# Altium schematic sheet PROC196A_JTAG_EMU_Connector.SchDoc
size 431 x 279 mm; Date: Not shown in title block; ApprovedBy: Not shown in title block; CheckedBy: Not shown in title block; Author: Not shown in title block; CompanyName: Not shown in title block; Engineer: Not shown in title block; Organization: Not shown in title block; Address1: Not shown in title block; Address2: Not shown in title block; Address3: Not shown in title block; Address4: Not shown in title block; DocumentNumber: 20; Revision: Use project parameter SCH_Rev; SheetNumber: 20; SheetTotal: 25; PageSetup: Record=PageOptions¦CenterHorizontal=True¦CenterVertical=True¦PrintScale=1.00¦XCorrection=1.00¦YCorrection=1.00¦PrintKind=0¦BorderSize=5000000¦LeftOffset=0¦BottomOffset=0¦Orientation=2¦PaperLength=1000¦PaperWidth=1000¦Scale=100¦PaperSource=15¦PrintQuality=600¦MediaType=1¦DitherType=10¦PaperKind=Letter¦PrintScaleMode=1
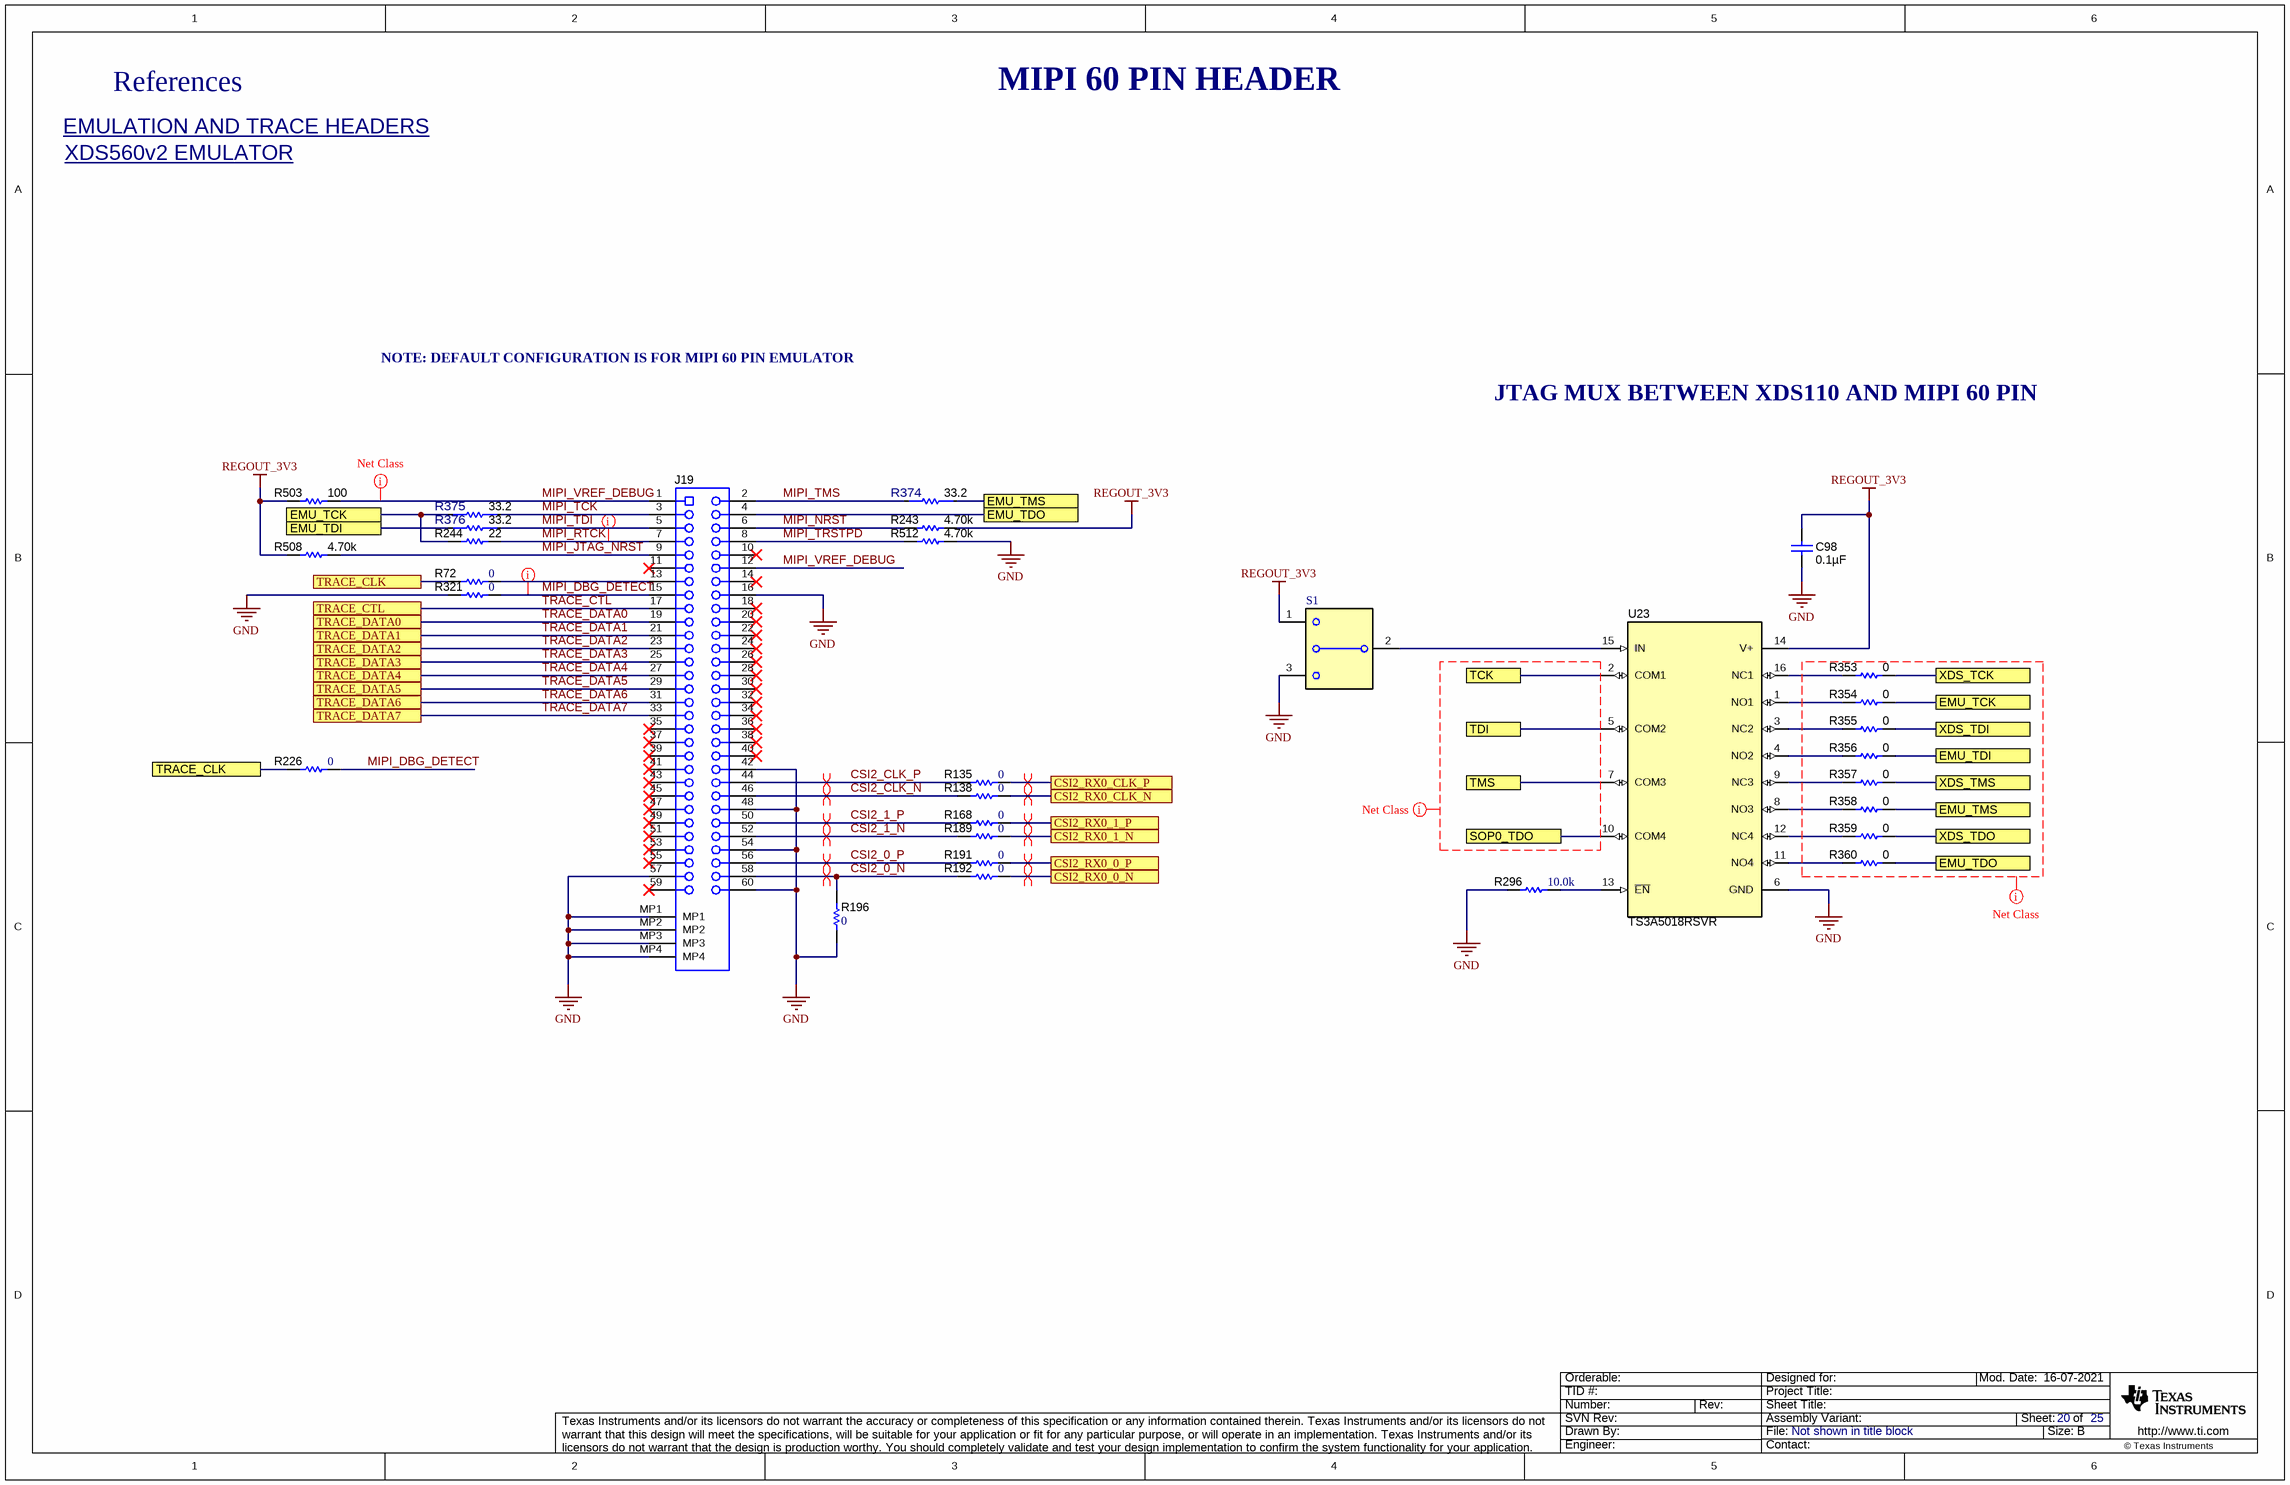
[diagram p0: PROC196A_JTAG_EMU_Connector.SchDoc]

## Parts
C98  ValueDisplayed: 0.1µF  [0402L]  (hidden comment: C0402C104K8RACTU)
J19  Receptacle_30x2_4MP_LeftRight  [Samtec_QSH-030-01-X-D-A]  (value not drawn)
R72  ValueDisplayed: 0  [0201L]  (hidden comment: CRCW02010000Z0ED)
R135  ValueDisplayed: 0  [0201L]  (hidden comment: CRCW02010000Z0ED)
R138  ValueDisplayed: 0  [0201L]  (hidden comment: CRCW02010000Z0ED)
R168  ValueDisplayed: 0  [0201L]  (hidden comment: CRCW02010000Z0ED)
R189  ValueDisplayed: 0  [0201L]  (hidden comment: CRCW02010000Z0ED)
R191  ValueDisplayed: 0  [0201L]  (hidden comment: CRCW02010000Z0ED)
R192  ValueDisplayed: 0  [0201L]  (hidden comment: CRCW02010000Z0ED)
R196  ValueDisplayed: 0  [0201L]  (hidden comment: CRCW02010000Z0ED)
R226  ValueDisplayed: 0  [0201L]  (hidden comment: CRCW02010000Z0ED)
R243  ValueDisplayed: 4.70k  [0201_033L]  (hidden comment: CRCW02014K70FKED)
R244  ValueDisplayed: 22  [0201L]  (hidden comment: ERJ-1GNJ220C)
R296  ValueDisplayed: 10.0k  [0402L]  (hidden comment: CRCW040210K0FKED)
R321  ValueDisplayed: 0  [0201L]  (hidden comment: CRCW02010000Z0ED)
R353  ValueDisplayed: 0  [0402L]  (hidden comment: ERJ-2GE0R00X)
R354  ValueDisplayed: 0  [0402L]  (hidden comment: ERJ-2GE0R00X)
R355  ValueDisplayed: 0  [0402L]  (hidden comment: ERJ-2GE0R00X)
R356  ValueDisplayed: 0  [0402L]  (hidden comment: ERJ-2GE0R00X)
R357  ValueDisplayed: 0  [0402L]  (hidden comment: ERJ-2GE0R00X)
R358  ValueDisplayed: 0  [0402L]  (hidden comment: ERJ-2GE0R00X)
R359  ValueDisplayed: 0  [0402L]  (hidden comment: ERJ-2GE0R00X)
R360  ValueDisplayed: 0  [0402L]  (hidden comment: ERJ-2GE0R00X)
R374  Res_ohm: 33.2  [FP-ERJ-1GNF33R2C_0201-MFG]  (hidden comment: ERJ-1GNF33R2C)
R375  Res_ohm: 33.2  [FP-ERJ-1GNF33R2C_0201-MFG]  (hidden comment: ERJ-1GNF33R2C)
R376  Res_ohm: 33.2  [FP-ERJ-1GNF33R2C_0201-MFG]  (hidden comment: ERJ-1GNF33R2C)
R503  ValueDisplayed: 100  [0201L]  (hidden comment: CRCW0201100RFKED)
R508  ValueDisplayed: 4.70k  [0201_033L]  (hidden comment: CRCW02014K70FKED)
R512  ValueDisplayed: 4.70k  [0201_033L]  (hidden comment: CRCW02014K70FKED)
S1  CJS-1201TA  [SW_CJS_1201A]  (value not drawn)
U23  TS3A5018RSVR  [RSV0016A]

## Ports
CSI2_RX0_0_N, CSI2_RX0_0_P, CSI2_RX0_1_N, CSI2_RX0_1_P, CSI2_RX0_CLK_N, CSI2_RX0_CLK_P, EMU_TCK, EMU_TDI, EMU_TDO, EMU_TMS, SOP0_TDO, TCK, TDI, TMS, TRACE_CLK, TRACE_CTL, TRACE_DATA0, TRACE_DATA1, TRACE_DATA2, TRACE_DATA3, TRACE_DATA4, TRACE_DATA5, TRACE_DATA6, TRACE_DATA7, XDS_TCK, XDS_TDI, XDS_TDO, XDS_TMS

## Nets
GND: C98.1 J19.16 J19.42 J19.48 J19.54 J19.57 J19.60 J19.MP1 J19.MP2 J19.MP3 J19.MP4 R196.2 R296.2 R321.1 R512.2 S1.3 U23.6(GND)
REGOUT_3V3: C98.2 R243.2 R503.1 R508.1 S1.1 U23.14(V+)
CSI2_0_N: J19.58 R192.2 R196.1
CSI2_0_P: J19.56 R191.2
CSI2_1_N: J19.52 R189.2
CSI2_1_P: J19.50 R168.2
CSI2_CLK_N: J19.46 R138.2
CSI2_CLK_P: J19.44 R135.2
CSI2_RX0_0_N: R192.1 ; port CSI2_RX0_0_N
CSI2_RX0_0_P: R191.1 ; port CSI2_RX0_0_P
CSI2_RX0_1_N: R189.1 ; port CSI2_RX0_1_N
CSI2_RX0_1_P: R168.1 ; port CSI2_RX0_1_P
CSI2_RX0_CLK_N: R138.1 ; port CSI2_RX0_CLK_N
CSI2_RX0_CLK_P: R135.1 ; port CSI2_RX0_CLK_P
EMU_TCK: R244.1 R354.1 R375.2 ; port EMU_TCK
EMU_TDI: R356.1 R376.2 ; port EMU_TDI
EMU_TDO: J19.4 R360.1 ; port EMU_TDO
EMU_TMS: R358.1 R374.1 ; port EMU_TMS
MIPI_DBG_DETECT: J19.15 R226.2 R321.2
MIPI_JTAG_NRST: J19.9 R508.2
MIPI_NRST: J19.6 R243.1
MIPI_RTCK: J19.7 R244.2
MIPI_TCK: J19.3 R375.1
MIPI_TDI: J19.5 R376.1
MIPI_TMS: J19.2 R374.2
MIPI_TRSTPD: J19.8 R512.1
MIPI_VREF_DEBUG: J19.1 J19.12 R503.2
SOP0_TDO: U23.10(COM4) ; port SOP0_TDO
TCK: U23.2(COM1) ; port TCK
TDI: U23.5(COM2) ; port TDI
TMS: U23.7(COM3) ; port TMS
TRACE_CLK: R72.1 R226.1 ; port TRACE_CLK
TRACE_CTL: J19.17 ; port TRACE_CTL
TRACE_DATA0: J19.19 ; port TRACE_DATA0
TRACE_DATA1: J19.21 ; port TRACE_DATA1
TRACE_DATA2: J19.23 ; port TRACE_DATA2
TRACE_DATA3: J19.25 ; port TRACE_DATA3
TRACE_DATA4: J19.27 ; port TRACE_DATA4
TRACE_DATA5: J19.29 ; port TRACE_DATA5
TRACE_DATA6: J19.31 ; port TRACE_DATA6
TRACE_DATA7: J19.33 ; port TRACE_DATA7
XDS_TCK: R353.1 ; port XDS_TCK
XDS_TDI: R355.1 ; port XDS_TDI
XDS_TDO: R359.1 ; port XDS_TDO
XDS_TMS: R357.1 ; port XDS_TMS
NetJ19_13: J19.13 R72.2
NetR296_1: R296.1 U23.13(~{EN})
NetR353_2: R353.2 U23.16(NC1)
NetR354_2: R354.2 U23.1(NO1)
NetR355_2: R355.2 U23.3(NC2)
NetR356_2: R356.2 U23.4(NO2)
NetR357_2: R357.2 U23.9(NC3)
NetR358_2: R358.2 U23.8(NO3)
NetR359_2: R359.2 U23.12(NC4)
NetR360_2: R360.2 U23.11(NO4)
NetS1_2: S1.2(COM) U23.15(IN)

Not connected (* = marked no-connect by the designer): J19 10* 11* 14* 18* 20* 22* 24* 26* 28* 30* 32* 34* 35* 36* 37* 38* 39* 40* 41* 43* 45* 47* 49* 51* 53* 55* 59*

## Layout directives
net class JTAG: (no net found under the mark), MIPI_RTCK
net class TRACE: MIPI_DBG_DETECT
net class PWR: MIPI_VREF_DEBUG
differential pair: CSI2_0_N, CSI2_0_P, CSI2_1_N, CSI2_1_P, CSI2_CLK_N, CSI2_CLK_P, CSI2_RX0_0_N, CSI2_RX0_0_P, CSI2_RX0_1_N, CSI2_RX0_1_P, CSI2_RX0_CLK_N, CSI2_RX0_CLK_P

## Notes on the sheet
- References
- MIPI 60 PIN HEADER
- XDS560v2 EMULATOR <http://www.spectrumdigital.com/xds560v2-system-trace-jtag-emulator-with-target-adapters/>
- EMULATION AND TRACE HEADERS <http://www.ti.com/lit/ug/spru655i/spru655i.pdf>
- NOTE: DEFAULT CONFIGURATION IS FOR MIPI 60 PIN EMULATOR
- JTAG MUX BETWEEN XDS110 AND MIPI 60 PIN

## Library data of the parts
C98 = CMP-0078241-1: CAP, CERM, 0.1 µF, 10 V,+/- 10%, X7R, 0402; Manufacturer: Kemet; TaMin_C: -55°C; Polarized: N; SizeAreaWB_mm2: 3; U/M: EA; Value: 0.1uF; TaMax_C: 125°C; SizeZ_mm: 0.6; SizeX_mm: 1; SizeY_mm: 0.5; Cap_Case: 0402; Value2: 10V; Cap_F: 100nF; AEC Category: Q200
J19 = CMP-0075524-1: Receptacle, 0.5 mm, 30x2, Gold, TH; PartNumber: QSH-030-01-L-D-A; Manufacturer: Samtec; Pitch_mm: 0.5; Gender: Female; Shrouded: N; Row_Count: 2; RowSpacing_mm: 5.73; Green_Lifecycle: Active; Green_REACh: Passed; CNHeader: False
R72 R135 R138 R168 R189 R191 R192 R196 R226 R321 = CMP-0027008-4: RES, 0, 5%, 0.05 W, 0201; Manufacturer: Vishay-Dale; Power_W: 50mW; TempCo: ppm/C; Value_Code: 0000; Value: 0; EIA_Code: E24; SizeX_mm: 0.6; SizeY_mm: 0.3; SizeZ_mm: 0.26; Value2: 0.05W; SizeArea_mm2: 0.18; AEC Qualified: N; AEC Category: Q200
R243 R508 R512 = CMP-0027280-3: RES, 4.70 k, 1%, 0.05 W, 0201; Manufacturer: Vishay-Dale; Power_W: 50mW; TempCo: 100 ppm/C; Value_Code: 4k70; Value: 4.70k; Res_ohm: 4.7k; SizeX_mm: 0.6; SizeY_mm: 0.3; SizeZ_mm: 0.33; Value2: 0.05W; SizeArea_mm2: 0.18; AEC Qualified: N; VDC_V: 30V; AEC Category: Q200
R244 = CMP-0027015-3: RES, 22, 5%, 0.05 W, AEC-Q200 Grade 1, 0201; Manufacturer: Panasonic; Power_W: 50mW; TempCo: 200 ppm/C; Value_Code: 22R0; U/M: EA; Value: 22; EIA_Code: E24; SizeX_mm: 0.6; SizeY_mm: 0.3; SizeZ_mm: 0.26; Value2: 0.05W; SizeArea_mm2: 0.18; AEC Qualified: Y; AEC Grade: 1; AEC Category: Q200
R296 = CMP-0025958-3: RES, 10.0 k, 1%, 0.063 W, AEC-Q200 Grade 0, 0402; Manufacturer: Vishay-Dale; Power_W: 63mW; TempCo: 100 ppm/C; Value_Code: 10k0; Value: 10.0k; EIA_Code: E96; Res_ohm: 10k; SizeX_mm: 1; SizeY_mm: 0.5; SizeZ_mm: 0.6; Value2: 0.063W; AEC Qualified: Y; VDC_V: 50V; AEC Category: Q200; AEC Grade: 0
R353-R360 = CMP-0026992-3: RES, 0, 5%, 0.1 W, AEC-Q200 Grade 0, 0402; Manufacturer: Panasonic; Power_W: 100mW; TempCo: 600 ppm/C; Value_Code: 0000; Value: 0; EIA_Code: E24; SizeX_mm: 1; SizeY_mm: 0.5; SizeZ_mm: 0.6; Value2: 0.1W; AEC Qualified: Y; VDC_V: 50V; AEC Category: Q200; SizeAreaWB_mm2: 3
R374-R376 = CMP-0089575-2: Res Thick Film 0201 33.2 Ohm 1% 0.05W(1/20W) ±200ppm/C Pad SMD Automotive T/R; Manufacturer: Panasonic; TempCo: 200ppm/°C; VDC_V: 25V; AEC Qualified: Yes; SizeZ_mm: 0.26mm; Power_W: 50mW; AEC Grade: Grade 1; Value: 33.2
R503 = CMP-0083836-1: RES, 100, 1%, 0.05 W, 0201; Manufacturer: Vishay-Semiconductor; Value_Code: 100R; SizeAreaWB_mm2: 2.08; SizeArea_mm2: 0.18; AEC Qualified: N; AEC Category: Q200; Value: 100; SizeZ_mm: 0.26; EIA_Code: E96; TempCo: 100 ppm/C; Power_W: 50mW; SizeY_mm: 0.3; Value2: 0.05W; SizeX_mm: 0.6
S1 = CMP-0002159-2: Slide SW, SPDT 0.1A 50VDC; Manufacturer: Copal Electronics; CurrentRating_mA: 100A; SwitchFunction: On-Off-On; VDC_V: 50V; PositionCount: 1; CompType: Switch
U23 = CMP-0067415-1: 10-Ohm Quad SPDT Analog Switch, RSV0016A (UQFN-16); Alternate Manufacturer: Texas Instruments; SizeAreaWB_mm2: 10.08; U/M: EA; SizeZ_mm: 0.55; SizeX_mm: 1.8; SizeY_mm: 2.6; SizeArea_mm2: 4.68; CompType: IC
